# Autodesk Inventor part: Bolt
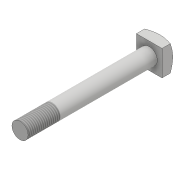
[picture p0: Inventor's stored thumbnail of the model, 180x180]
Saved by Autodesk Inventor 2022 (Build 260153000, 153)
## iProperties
Created: 2016-05
Part Number: Bolt
Material: Generic
Document SubType Name: Modeling
Designer: CADCIM
Density: 1 g/cm^3
Appearance: Default
Author: CADCIM
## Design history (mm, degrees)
sketch "Sketch1"
  geometry: L1 (9.5, 9.5)-(-9.5, 9.5); L2 (-9.5, 9.5)-(-9.5, -9.5); L3 (-9.5, -9.5)-(9.5, -9.5); L4 (9.5, -9.5)-(9.5, 9.5); L5 (0, 0)-(0, 14.108); L6 (0, 0)-(-17.802, 0)
  constraints: 12 end point, 2 horizontal, 2 parallel, 2 perpendicular, 1 vertical, 2 other
  dimensions: "d0" = 19 distance of L3.end L1.start
extrude "Extrusion1" new body sketch "Sketch1" distance "d1" = 8; taper "d2" = 0 deg
sketch "Sketch3"
  geometry: L1 (9.5, 9.5)-(-9.5, 9.5) reference; C1 r 9.5 at (0, 0); 1 further point
  constraints: 1 centre point, 1 coincident, 1 tangent
extrude "Extrusion3" sketch "Sketch3" distance "d6" = 96; taper "d7" = 65 deg
sketch "Sketch4"
  geometry: C1 r 6 at (0, 0); 1 further point
  constraints: 1 centre point, 1 coincident
  dimensions: "d10" = 12 diameter of C1
extrude "Extrusion4" join sketch "Sketch4" distance "d11" = 96; taper "d12" = 0 deg
thread "Thread2" dims "d13" = 24, "d14" = 0
body "Solid1"
